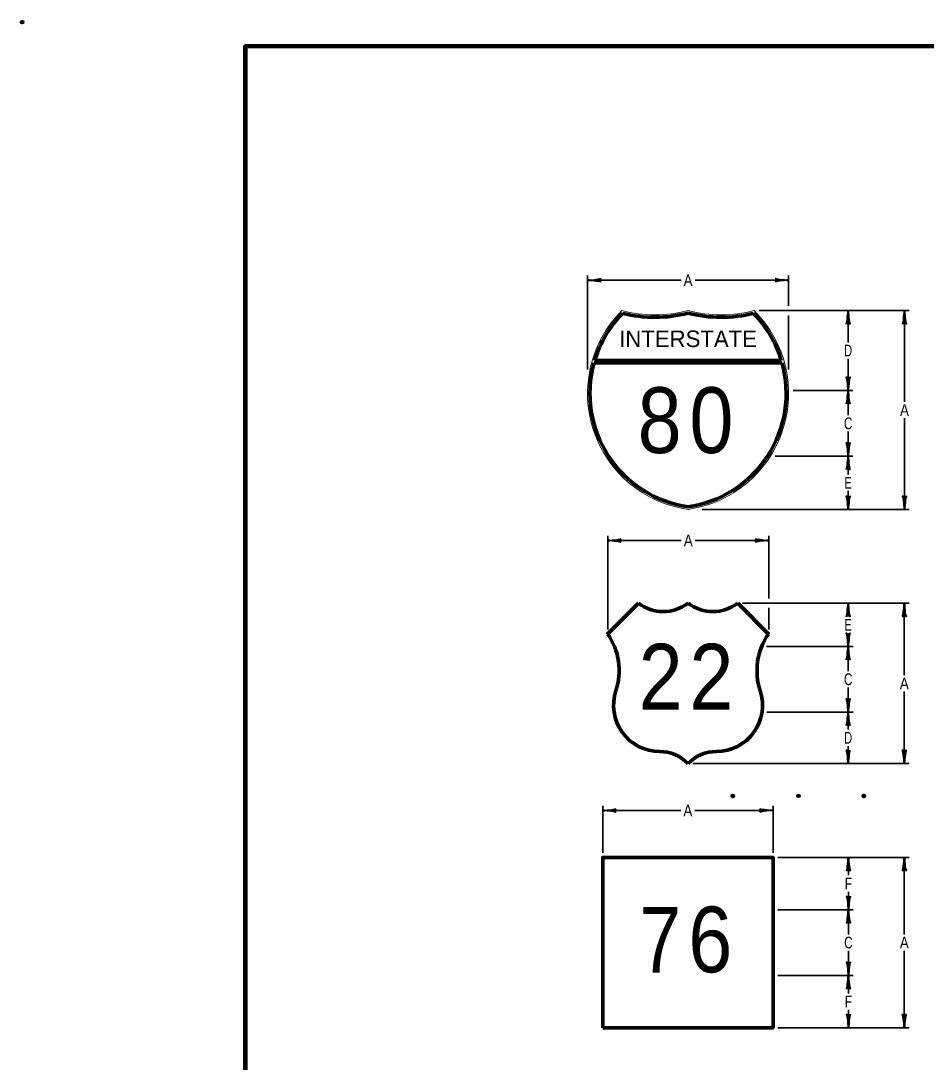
# Model space of a CAD drawing. Extents: x -96 to 760, y -448 to 96.
# Drawn here: x -95.9 to 135.6, y -170.2 to 96.1 of the extents above; entities that cross this region are included whole.
import ezdxf
from ezdxf.enums import TextEntityAlignment as Align

# ---------------------------------------------------------------- set-up
doc = ezdxf.new("R2010")
doc.units = 0
doc.header["$LTSCALE"] = 1.4
doc.header["$PDMODE"] = 32
doc.header["$PDSIZE"] = 0.7
doc.layers.add('1', color=7, linetype='Continuous', lineweight=40)

msp = doc.modelspace()

# ---------------------------------------------------------------- linework, layer by layer
at = {"layer": '1', "lineweight": 35}
for p, q in [((48.965, 6.982), (48.965, 30.982)), ((48.965, 29.782), (72.877, 29.782)), ((76.477, 29.782), (100.389, 29.782)), ((100.389, 23.194), (100.389, 30.982)), ((92.818, 21.994), (131.218, 21.994)), ((115.618, 13.894), (115.618, 21.994)), ((130.018, 21.994), (130.018, -1.318)), ((100.389, 6.982), (100.389, 20.794)), ((115.618, 1.594), (115.618, 9.694)), ((101.58, 1.594), (116.818, 1.594)), ((115.618, 1.594), (115.618, -4.706)), ((130.018, -5.518), (130.018, -28.83)), ((96.943, -15.206), (116.818, -15.206)), ((115.618, -24.118), (115.618, -28.83)), ((78.277, -28.83), (131.218, -28.83)), ((54.146, -59.491), (54.146, -35.57)), ((54.146, -36.77), (72.934, -36.77)), ((76.535, -36.77), (95.323, -36.77)), ((95.323, -51.63), (95.323, -35.57)), ((88.583, -52.83), (131.171, -52.83)), ((115.618, -56.239), (115.618, -52.83)), ((129.971, -52.83), (129.971, -71.216)), ((95.323, -59.57), (95.323, -54.03)), ((115.618, -63.849), (115.618, -60.439)), ((116.885, -63.849), (94.706, -63.849)), ((115.618, -63.849), (115.618, -70.149)), ((129.971, -75.416), (129.971, -93.802)), ((116.885, -80.649), (94.807, -80.649)), ((115.618, -89.325), (115.618, -93.802)), ((75.925, -93.802), (131.171, -93.802)), ((52.849, -116.602), (52.849, -104.602)), ((52.849, -105.802), (72.829, -105.802)), ((76.429, -105.802), (96.409, -105.802)), ((96.409, -116.602), (96.409, -104.602)), ((97.609, -117.802), (131.171, -117.802)), ((115.685, -122.392), (115.685, -117.802)), ((129.971, -117.802), (129.971, -137.482)), ((115.685, -131.182), (115.685, -126.592)), ((97.609, -131.182), (116.885, -131.182)), ((115.685, -131.182), (115.685, -137.482)), ((129.971, -141.682), (129.971, -161.362)), ((97.609, -147.982), (116.885, -147.982)), ((115.685, -156.772), (115.685, -161.362)), ((97.609, -161.362), (131.171, -161.362))]:
    msp.add_line(p, q, dxfattribs=at)
at = {"layer": '1', "lineweight": 70}
for p, q in [((50.661, 8.659), (98.693, 8.659)), ((98.511, 9.288), (50.843, 9.288)), ((54.031, -60.77), (61.971, -52.83)), ((87.383, -52.83), (95.323, -60.77))]:
    msp.add_line(p, q, dxfattribs=at)
at = {"layer": '1', "lineweight": 158}
msp.add_lwpolyline([(753.127, 89.656), (-38.573, 89.556), (-38.473, -436.444)], dxfattribs=at)
at = {"layer": '1', "lineweight": 35}
for points in [[(115.618, -8.906), (115.618, -15.206), (115.618, -19.918)], [(115.618, -74.349), (115.618, -80.649), (115.618, -85.125)], [(115.685, -141.682), (115.685, -147.982), (115.685, -152.572)]]:
    msp.add_lwpolyline(points, dxfattribs=at)
at = {"layer": '1', "lineweight": 70}
msp.add_lwpolyline([(52.849, -161.362), (52.849, -117.802), (96.409, -117.802), (96.409, -161.362)], close=True, dxfattribs=at)
at = {"layer": '1', "lineweight": 13}
for centre, radius, start, end in [((78.912, 0.817), 29.948, 135, 261.8699), ((66.206, 55.347), 34.412, 255.74997, 284.25003), ((83.148, 55.347), 34.412, 255.74997, 284.25003), ((70.442, 0.817), 29.948, 278.1301, 45)]:
    msp.add_arc(centre, radius, start, end, dxfattribs=at)
at = {"layer": '1', "lineweight": 70}
for centre, radius, start, end in [((66.206, 55.347), 35.041, 256.3405, 283.98896), ((83.148, 55.347), 35.041, 256.01104, 283.6595), ((78.912, 0.817), 29.319, 135.69236, 163.20725), ((70.442, 0.817), 29.319, 16.79275, 44.30764), ((78.912, 0.817), 29.319, 164.48686, 261.8699), ((70.442, 0.817), 29.319, 278.1301, 15.51314), ((68.324, -44.358), 10.59, 233.13599, 306.864), ((81.03, -44.358), 10.59, 233.136, 306.86401), ((40.588, -70.035), 16.466, 341.82892, 34.57472), ((108.766, -70.035), 16.466, 145.42527, 198.17107), ((67.418, -78.923), 11.798, 161.45202, 269.9953), ((81.936, -78.923), 11.798, 270.0047, 18.54798), ((67.417, -100.701), 9.981, 43.72746, 90), ((81.937, -100.701), 9.981, 90, 136.27254)]:
    msp.add_arc(centre, radius, start, end, dxfattribs=at)
at = {"layer": '1'}
for centre, major_axis, ratio, start_param, end_param in [((50.309, 29.528), (-2.108, 0.211), 0.07063, 3.1407148, 5.41811), ((50.274, 30.114), (-2.143, -0.187), 0.122415, 0.8963533, 3.1415927), ((99.08, 29.451), (2.143, 0.187), 0.122415, 0.8963533, 3.1415927), ((99.08, 29.451), (2.143, 0.187), 0.122415, 0.8963533, 3.1415927), ((99.045, 30.036), (2.108, -0.211), 0.07063, 3.1407148, 5.41811), ((99.045, 30.036), (2.108, -0.211), 0.07063, 3.1407148, 5.41811), ((115.364, 20.649), (0.211, 2.108), 0.07063, 3.1407148, 5.41811), ((115.364, 20.649), (0.211, 2.108), 0.07063, 3.1407148, 5.41811), ((115.95, 20.684), (-0.187, 2.143), 0.122415, 0.8963533, 3.1415927), ((115.95, 20.684), (-0.187, 2.143), 0.122415, 0.8963533, 3.1415927), ((129.764, 20.649), (0.211, 2.108), 0.07063, 3.1407148, 5.41811), ((129.764, 20.649), (0.211, 2.108), 0.07063, 3.1407148, 5.41811), ((130.35, 20.684), (-0.187, 2.143), 0.122415, 0.8963533, 3.1415927), ((130.35, 20.684), (-0.187, 2.143), 0.122415, 0.8963533, 3.1415927), ((115.287, 2.903), (0.187, -2.143), 0.122415, 0.8963533, 3.1415927), ((115.287, 2.903), (0.187, -2.143), 0.122415, 0.8963533, 3.1415927), ((115.872, 2.938), (-0.211, -2.108), 0.07063, 3.1407148, 5.41811), ((115.872, 2.938), (-0.211, -2.108), 0.07063, 3.1407148, 5.41811), ((115.364, 0.249), (0.211, 2.108), 0.07063, 3.1407148, 5.41811), ((115.364, 0.249), (0.211, 2.108), 0.07063, 3.1407148, 5.41811), ((115.95, 0.284), (-0.187, 2.143), 0.122415, 0.8963533, 3.1415927), ((115.95, 0.284), (-0.187, 2.143), 0.122415, 0.8963533, 3.1415927), ((115.287, -13.897), (0.187, -2.143), 0.122415, 0.8963533, 3.1415927), ((115.287, -13.897), (0.187, -2.143), 0.122415, 0.8963533, 3.1415927), ((115.872, -13.862), (-0.211, -2.108), 0.07063, 3.1407148, 5.41811), ((115.872, -13.862), (-0.211, -2.108), 0.07063, 3.1407148, 5.41811), ((115.364, -16.551), (0.211, 2.108), 0.07063, 3.1407148, 5.41811), ((115.364, -16.551), (0.211, 2.108), 0.07063, 3.1407148, 5.41811), ((115.95, -16.516), (-0.187, 2.143), 0.122415, 0.8963533, 3.1415927), ((115.95, -16.516), (-0.187, 2.143), 0.122415, 0.8963533, 3.1415927), ((115.287, -27.52), (0.187, -2.143), 0.122415, 0.8963533, 3.1415927), ((115.287, -27.52), (0.187, -2.143), 0.122415, 0.8963533, 3.1415927), ((115.872, -27.485), (-0.211, -2.108), 0.07063, 3.1407148, 5.41811), ((115.872, -27.485), (-0.211, -2.108), 0.07063, 3.1407148, 5.41811), ((129.687, -27.52), (0.187, -2.143), 0.122415, 0.8963533, 3.1415927), ((129.687, -27.52), (0.187, -2.143), 0.122415, 0.8963533, 3.1415927), ((130.272, -27.485), (-0.211, -2.108), 0.07063, 3.1407148, 5.41811), ((130.272, -27.485), (-0.211, -2.108), 0.07063, 3.1407148, 5.41811), ((55.455, -36.438), (-2.143, -0.187), 0.122415, 0.8963533, 3.1415927), ((55.455, -36.438), (-2.143, -0.187), 0.122415, 0.8963533, 3.1415927), ((55.491, -37.024), (-2.108, 0.211), 0.07063, 3.1407148, 5.41811), ((55.491, -37.024), (-2.108, 0.211), 0.07063, 3.1407148, 5.41811), ((94.014, -37.101), (2.143, 0.187), 0.122415, 0.8963533, 3.1415927), ((93.978, -36.516), (2.108, -0.211), 0.07063, 3.1407148, 5.41811), ((115.364, -54.175), (0.211, 2.108), 0.07063, 3.1407148, 5.41811), ((115.364, -54.175), (0.211, 2.108), 0.07063, 3.1407148, 5.41811), ((115.95, -54.139), (-0.187, 2.143), 0.122415, 0.8963533, 3.1415927), ((115.95, -54.139), (-0.187, 2.143), 0.122415, 0.8963533, 3.1415927), ((129.717, -54.175), (0.211, 2.108), 0.07063, 3.1407148, 5.41811), ((130.302, -54.139), (-0.187, 2.143), 0.122415, 0.8963533, 3.1415927), ((115.287, -62.539), (0.187, -2.143), 0.122415, 0.8963533, 3.1415927), ((115.287, -62.539), (0.187, -2.143), 0.122415, 0.8963533, 3.1415927), ((115.872, -62.504), (-0.211, -2.108), 0.07063, 3.1407148, 5.41811), ((115.872, -62.504), (-0.211, -2.108), 0.07063, 3.1407148, 5.41811), ((115.364, -65.193), (0.211, 2.108), 0.07063, 3.1407148, 5.41811), ((115.364, -65.193), (0.211, 2.108), 0.07063, 3.1407148, 5.41811), ((115.95, -65.158), (-0.187, 2.143), 0.122415, 0.8963533, 3.1415927), ((115.95, -65.158), (-0.187, 2.143), 0.122415, 0.8963533, 3.1415927), ((115.287, -79.339), (0.187, -2.143), 0.122415, 0.8963533, 3.1415927), ((115.287, -79.339), (0.187, -2.143), 0.122415, 0.8963533, 3.1415927), ((115.872, -79.304), (-0.211, -2.108), 0.07063, 3.1407148, 5.41811), ((115.872, -79.304), (-0.211, -2.108), 0.07063, 3.1407148, 5.41811), ((115.364, -81.993), (0.211, 2.108), 0.07063, 3.1407148, 5.41811), ((115.364, -81.993), (0.211, 2.108), 0.07063, 3.1407148, 5.41811), ((115.95, -81.958), (-0.187, 2.143), 0.122415, 0.8963533, 3.1415927), ((115.95, -81.958), (-0.187, 2.143), 0.122415, 0.8963533, 3.1415927), ((115.287, -92.492), (0.187, -2.143), 0.122415, 0.8963533, 3.1415927), ((115.287, -92.492), (0.187, -2.143), 0.122415, 0.8963533, 3.1415927), ((115.872, -92.457), (-0.211, -2.108), 0.07063, 3.1407148, 5.41811), ((115.872, -92.457), (-0.211, -2.108), 0.07063, 3.1407148, 5.41811), ((129.639, -92.492), (0.187, -2.143), 0.122415, 0.8963533, 3.1415927), ((130.224, -92.457), (-0.211, -2.108), 0.07063, 3.1407148, 5.41811), ((54.194, -106.056), (-2.108, 0.211), 0.07063, 3.1407148, 5.41811), ((54.194, -106.056), (-2.108, 0.211), 0.07063, 3.1407148, 5.41811), ((54.159, -105.47), (-2.143, -0.187), 0.122415, 0.8963533, 3.1415927), ((54.159, -105.47), (-2.143, -0.187), 0.122415, 0.8963533, 3.1415927), ((95.1, -106.133), (2.143, 0.187), 0.122415, 0.8963533, 3.1415927), ((95.1, -106.133), (2.143, 0.187), 0.122415, 0.8963533, 3.1415927), ((95.065, -105.548), (2.108, -0.211), 0.07063, 3.1407148, 5.41811), ((95.065, -105.548), (2.108, -0.211), 0.07063, 3.1407148, 5.41811), ((115.431, -119.146), (0.211, 2.108), 0.07063, 3.1407148, 5.41811), ((115.431, -119.146), (0.211, 2.108), 0.07063, 3.1407148, 5.41811), ((116.017, -119.111), (-0.187, 2.143), 0.122415, 0.8963533, 3.1415927), ((116.017, -119.111), (-0.187, 2.143), 0.122415, 0.8963533, 3.1415927), ((129.717, -119.146), (0.211, 2.108), 0.07063, 3.1407148, 5.41811), ((129.717, -119.146), (0.211, 2.108), 0.07063, 3.1407148, 5.41811), ((130.302, -119.111), (-0.187, 2.143), 0.122415, 0.8963533, 3.1415927), ((130.302, -119.111), (-0.187, 2.143), 0.122415, 0.8963533, 3.1415927), ((115.353, -129.872), (0.187, -2.143), 0.122415, 0.8963533, 3.1415927), ((115.353, -129.872), (0.187, -2.143), 0.122415, 0.8963533, 3.1415927), ((115.939, -129.837), (-0.211, -2.108), 0.07063, 3.1407148, 5.41811), ((115.939, -129.837), (-0.211, -2.108), 0.07063, 3.1407148, 5.41811), ((115.431, -132.526), (0.211, 2.108), 0.07063, 3.1407148, 5.41811), ((115.431, -132.526), (0.211, 2.108), 0.07063, 3.1407148, 5.41811), ((116.017, -132.491), (-0.187, 2.143), 0.122415, 0.8963533, 3.1415927), ((116.017, -132.491), (-0.187, 2.143), 0.122415, 0.8963533, 3.1415927), ((115.353, -146.672), (0.187, -2.143), 0.122415, 0.8963533, 3.1415927), ((115.353, -146.672), (0.187, -2.143), 0.122415, 0.8963533, 3.1415927), ((115.939, -146.637), (-0.211, -2.108), 0.07063, 3.1407148, 5.41811), ((115.939, -146.637), (-0.211, -2.108), 0.07063, 3.1407148, 5.41811), ((115.431, -149.326), (0.211, 2.108), 0.07063, 3.1407148, 5.41811), ((115.431, -149.326), (0.211, 2.108), 0.07063, 3.1407148, 5.41811), ((116.017, -149.291), (-0.187, 2.143), 0.122415, 0.8963533, 3.1415927), ((116.017, -149.291), (-0.187, 2.143), 0.122415, 0.8963533, 3.1415927), ((115.353, -160.052), (0.187, -2.143), 0.122415, 0.8963533, 3.1415927), ((115.353, -160.052), (0.187, -2.143), 0.122415, 0.8963533, 3.1415927), ((115.939, -160.017), (-0.211, -2.108), 0.07063, 3.1407148, 5.41811), ((115.939, -160.017), (-0.211, -2.108), 0.07063, 3.1407148, 5.41811), ((129.639, -160.052), (0.187, -2.143), 0.122415, 0.8963533, 3.1415927), ((130.224, -160.017), (-0.211, -2.108), 0.07063, 3.1407148, 5.41811)]:
    msp.add_ellipse(centre, major_axis=major_axis, ratio=ratio, start_param=start_param, end_param=end_param, dxfattribs=at)
for p in [(-95.573, 95.756), (86.141, -102.099), (102.886, -102.051), (119.632, -102.099)]:
    msp.add_point(p, dxfattribs=at)

# ---------------------------------------------------------------- texts
for s, width, p in [('A', 0.85, (74.677, 28.282)), ('D', 0.7, (115.618, 10.294)), ('A', 0.85, (130.018, -4.918)), ('C', 0.75, (115.618, -8.306)), ('E', 0.7, (115.618, -23.518)), ('A', 0.85, (74.734, -38.27)), ('E', 0.7, (115.618, -59.839)), ('C', 0.75, (115.618, -73.749)), ('A', 0.85, (129.97, -74.816)), ('D', 0.7, (115.618, -88.725)), ('A', 0.85, (74.629, -107.302)), ('F', 0.75, (115.685, -125.992)), ('C', 0.75, (115.685, -141.082)), ('A', 0.85, (129.97, -141.082)), ('F', 0.75, (115.685, -156.172))]:
    msp.add_text(s, height=3, dxfattribs=dict(at, width=width)).set_placement(p, align=Align.CENTER)
msp.add_text('INTERSTATE', height=4.235, dxfattribs=at).set_placement((74.677, 12.682), align=Align.CENTER)
for s, width, p in [('8', 0.9, (61.786, -14.407)), ('0', 0.9, (75.035, -14.407)), ('2', 0.9, (62.06, -80.008)), ('2', 0.9, (75.035, -80.008)), ('7', 0.85, (62.245, -147.255)), ('6', 0.9, (74.747, -147.189))]:
    msp.add_text(s, height=16.8, dxfattribs=dict(at, width=width)).set_placement(p)

doc.saveas('drawing.dxf')
